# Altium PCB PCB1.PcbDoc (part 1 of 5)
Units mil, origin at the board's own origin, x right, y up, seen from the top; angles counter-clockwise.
Board outline 4463 x 4481 mil, 2 copper layers (Top Layer, Bottom Layer); 0 components, 111 nets, 310 pads, 0 vias.
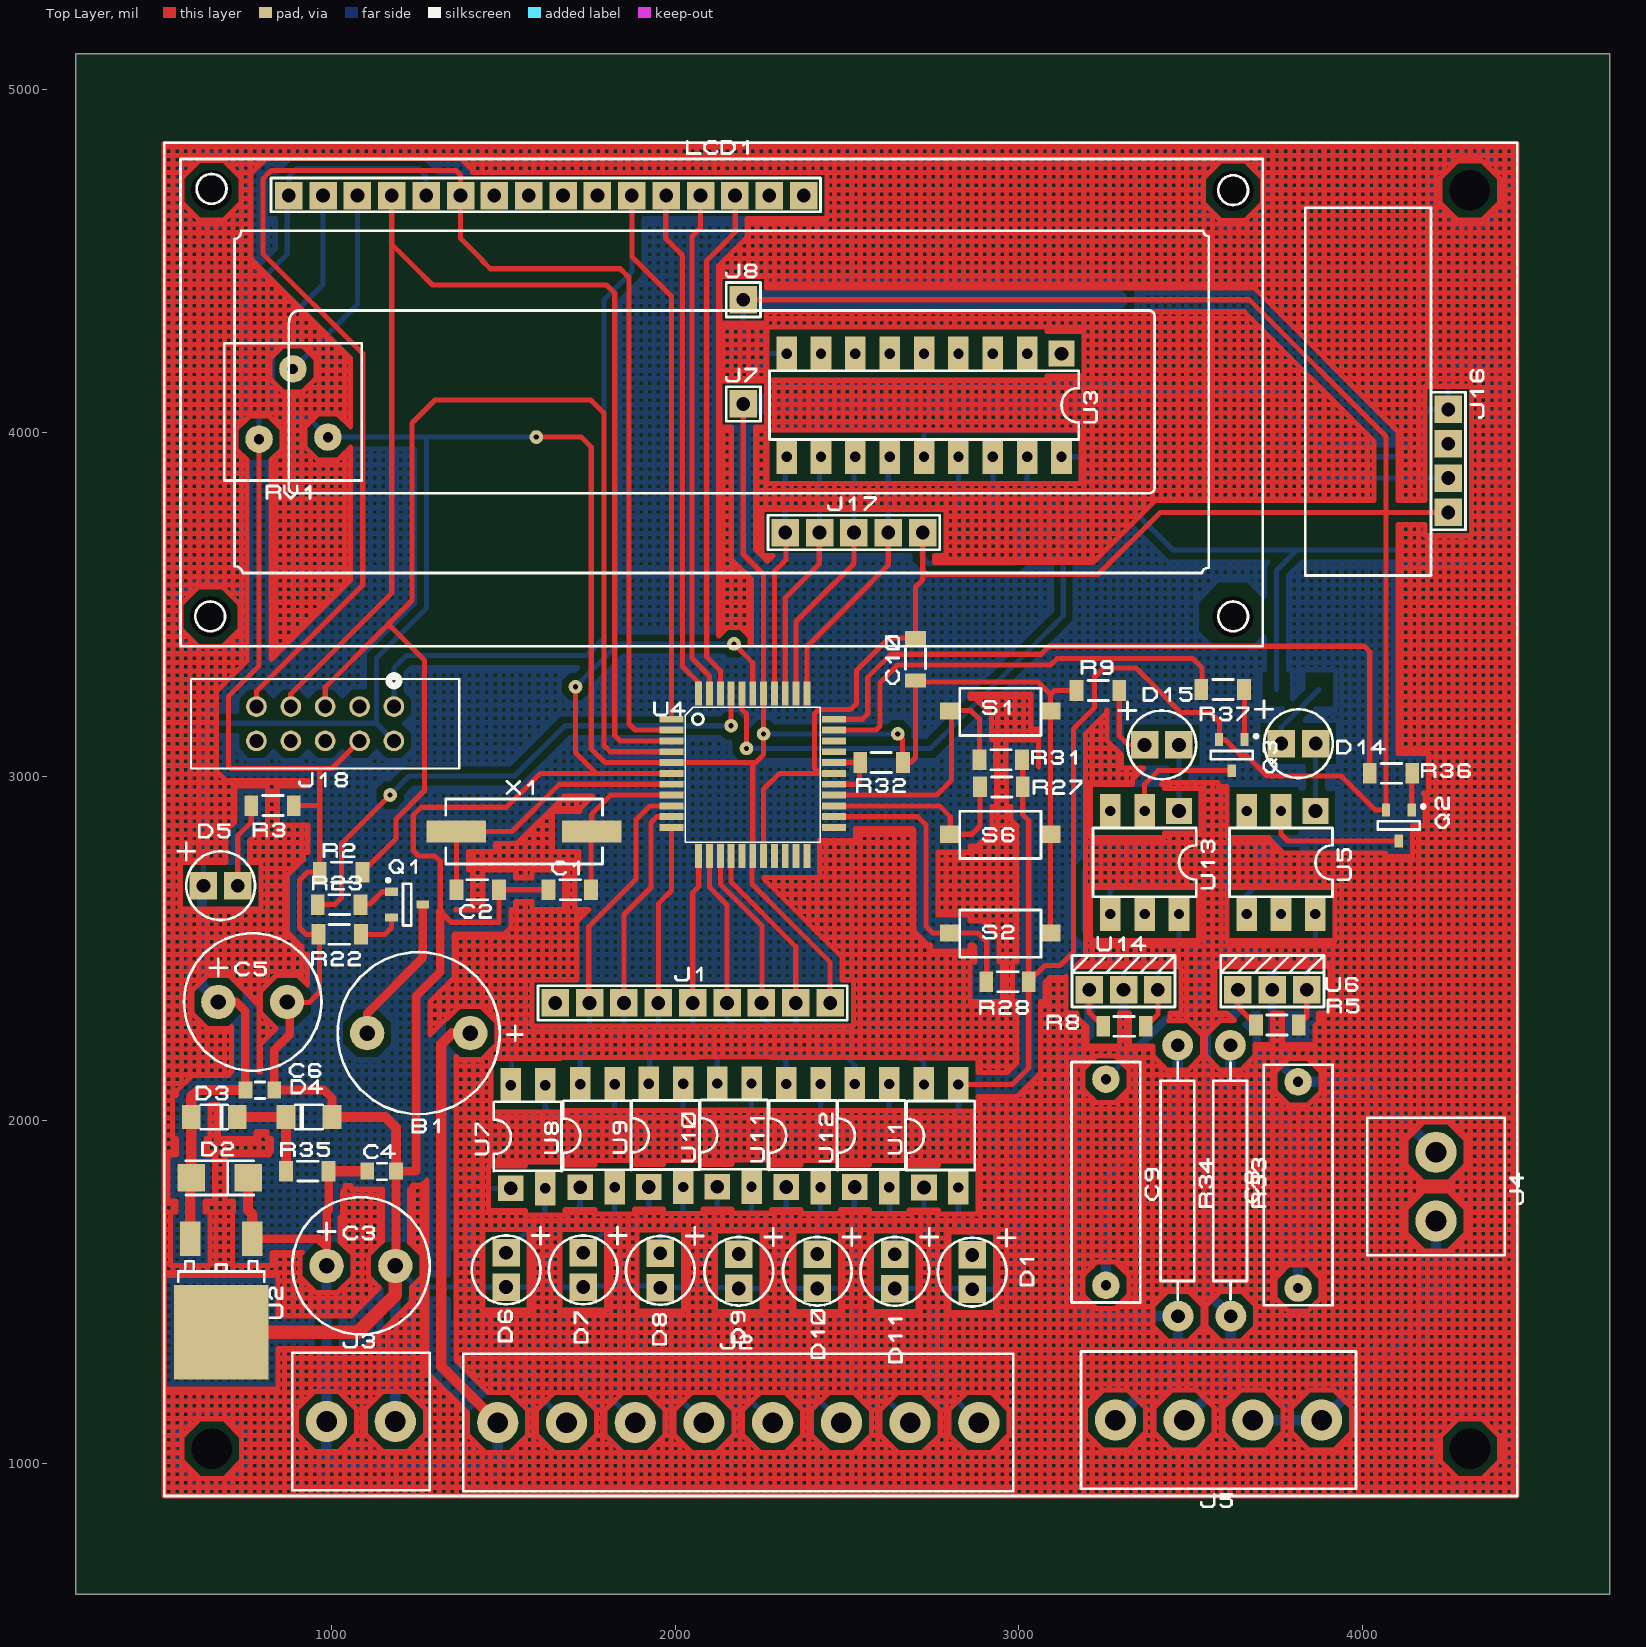
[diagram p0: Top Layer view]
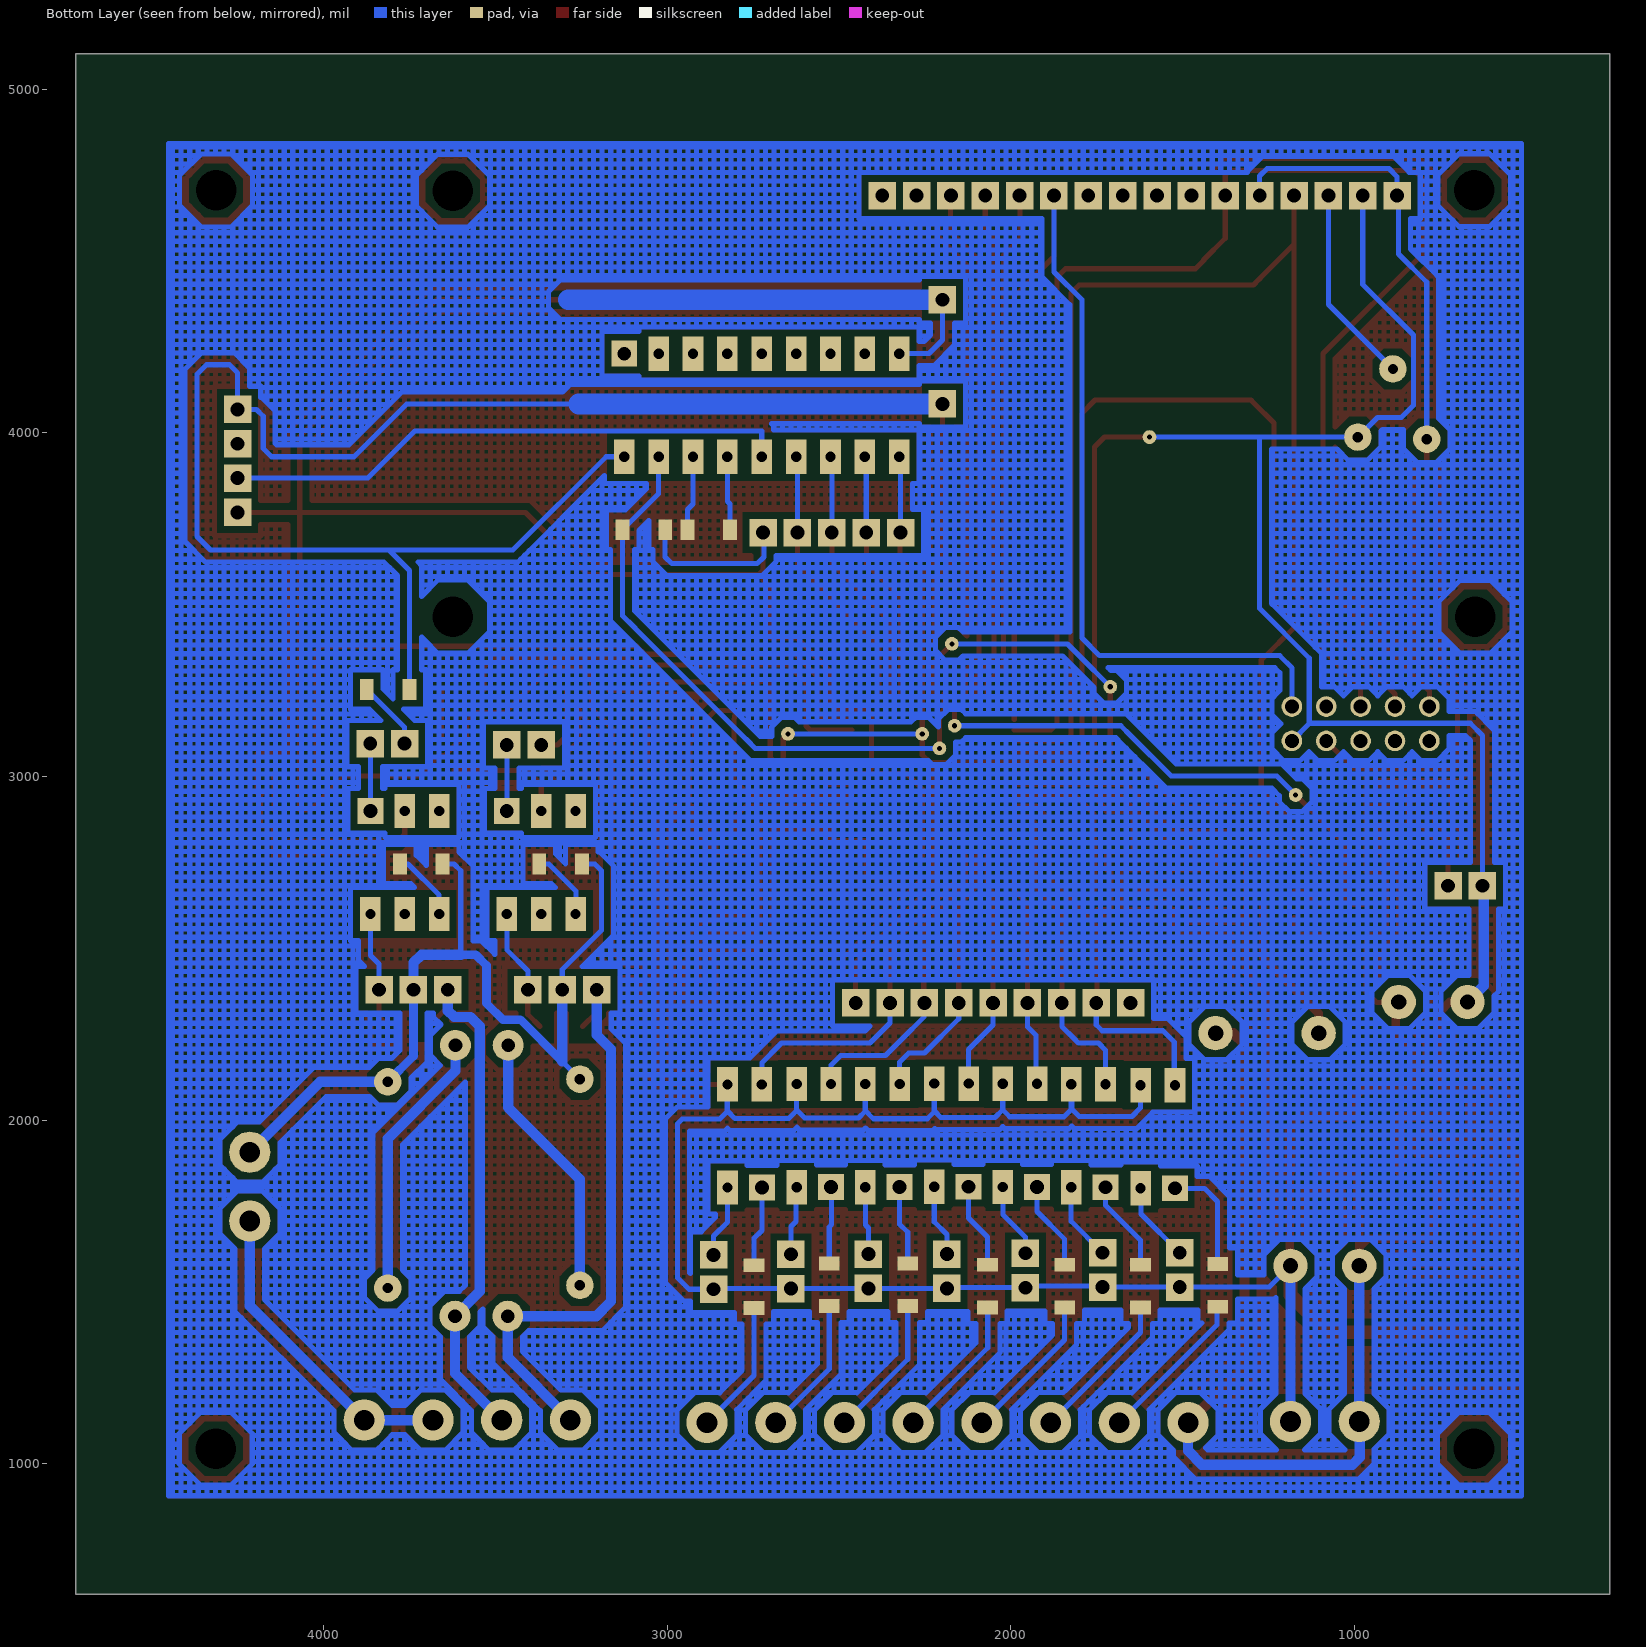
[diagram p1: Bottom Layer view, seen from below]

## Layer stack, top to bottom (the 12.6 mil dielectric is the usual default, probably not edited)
Top Layer: signal copper 1.4
Dielectric: dielectric 12.6, FR-4, Dk 4.8
Bottom Layer: signal copper 1.4

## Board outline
257,621 4720,621 4720,5102 257,5102

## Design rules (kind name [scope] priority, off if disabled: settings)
Clearance CAM_Clearance_2 [OnLayer('Top Layer')] p1: gap=0
Clearance CAM_Clearance_1 [OnLayer('Bottom Layer')] p2: gap=0
Clearance [All] p3: gap=10
PolygonConnect [All] p1: connectstyle=Relief reliefconductorwidth=10 reliefentries=4 polygonreliefangle="90 Angle"
RoutingVias [All] p1: holewidth=28 width=50 viastyle="Through Hole" minholewidth=28 minwidth=50 maxholewidth=28 maxwidth=50
SilkscreenOverComponentPads [All] p1: minsilkscreentomaskgap=10
SolderMaskExpansion [All] p1: expansion=4
Width CAM_Width_2 [OnLayer('Top Layer')] p1: maxlimit=41 minlimit=7 preferedwidth=8
Width CAM_Width_1 [OnLayer('Bottom Layer')] p2: maxlimit=61 minlimit=7 preferedwidth=8
Width [All] p3: maxlimit=10 minlimit=10 preferedwidth=10
27 further rules are at their usual default settings.

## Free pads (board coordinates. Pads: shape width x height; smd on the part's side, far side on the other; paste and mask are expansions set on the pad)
  rect 60x100 smd: 1(589.64,1654.6) 1(769.64,1654.6)
  rect 80x80 smd: 1(592.44,1831.7) 1(758.44,1831.7)
  rect 55x70 smd: 1(592.44,2008.9) 1(726.24,2008.9) 1(868.04,2008.9) 1(1001.84,2008.9)
  rect 80x80 hole 40: 1(627.84,2682.1) 1(727.84,2682.1) 1(875.94,4689.9) 1(975.94,4689.9) 1(1075.94,4689.9) 1(1175.94,4689.9) 1(1275.94,4689.9) 1(1375.94,4689.9) 1(1474.34,4689.9) 1(1508.54,1514) 1(1508.54,1614) 1(1574.34,4689.9) 1(1651.44,2340.8) 1(1674.34,4689.9) 1(1732.94,1514) 1(1732.94,1614) 1(1751.44,2340.8) 1(1774.34,4689.9) 1(1851.44,2340.8) 1(1874.34,4689.9) 1(1951.44,2340.8) 1(1957.34,1512.5) 1(1957.34,1612.5) 1(1974.34,4689.9) 1(2051.44,2340.8) 1(2074.34,4689.9) 1(2151.44,2340.8) 1(2174.34,4689.9) 1(2185.74,1510.1) 1(2185.74,1610.1) 1(2198.74,4083.6) 1(2198.74,4386.8) 1(2251.44,2340.8) 1(2274.34,4689.9) 1(2320.74,3709.6) 1(2351.44,2340.8) 1(2374.34,4689.9) 1(2414.04,1510.1) 1(2414.04,1610.1) 1(2420.74,3709.6) 1(2451.44,2340.8) 1(2520.64,3709.6) 1(2620.64,3709.6) 1(2639.54,1509.7) 1(2639.54,1609.7) 1(2720.64,3709.6) 1(2864.74,1507.7) 1(2864.74,1607.7) 1(3204.94,2379) 1(3304.94,2379) 1(3366.34,3091.5) 1(3404.94,2379) 1(3466.34,3091.5) 1(3638.04,2379) 1(3738.04,2379) 1(3763.94,3095.4) 1(3838.04,2379) 1(3863.94,3095.4) 1(4249.84,3767.9) 1(4249.84,3867.9) 1(4249.84,3967.9) 1(4249.84,4067.9)
  round 0 hole 118.1: 1(648.34,3464.3) 1(651.44,4705.7) 1(652.24,1043.6) 1(3623.44,3464.7) 1(3623.44,4704.1) 1(4312.44,4704.9) 1(4313.24,1043.6)
  round 100 hole 45: 1(671.14,2343.6) 1(871.14,2343.6) 1(986.14,1575.8) 1(1104.24,2253) 1(1186.14,1575.8) 1(1404.24,2253)
  rect 275x275 smd: 1(679.64,1382.6)
  rect 40x50 smd: 1(749.94,2087.6) 1(833.94,2087.6) 1(1104.24,1851.4) 1(1188.24,1851.4)
  rect 40x60 smd: 1(766.84,2915.1) 1(868.04,1851.4) 1(890.84,2915.1) 1(960.54,2627) 1(962.54,2540.4) 1(966.44,2721.5) 1(992.04,1851.4) 1(1084.54,2627) 1(1086.54,2540.4) 1(1090.44,2721.5) 1(1364.04,2670.3) 1(1488.04,2670.3) 1(1631.84,2670.3) 1(1755.84,2670.3) 1(2539.24,3040.3) 1(2663.24,3040.3) 1(2885.64,3048.2) 1(2887.64,2969.4) 1(2905.34,2402.6) 1(3009.64,3048.2) 1(3011.64,2969.4) 1(3029.34,2402.6) 1(3168.34,3250.1) 1(3245.84,2272.7) 1(3292.34,3250.1) 1(3369.84,2272.7) 1(3531.34,3252.9) 1(3655.34,3252.9) 1(3690.74,2276.6) 1(3814.74,2276.6) 1(4021.44,3008.8) 1(4145.44,3008.8)
  round 60 hole 40: 1(782.14,3103.3) 1(782.14,3203.3) 1(882.14,3103.3) 1(882.14,3203.3) 1(982.14,3103.3) 1(982.14,3203.3) 1(1082.14,3103.3) 1(1082.14,3203.3) 1(1182.14,3103.3) 1(1182.14,3203.3)
  round 80 hole 30: 1(789.64,3981.2) 1(888.14,4185.6) 1(990.04,3987.2) 1(3253.74,1519.1) 1(3253.74,2119.1) 1(3812.84,1511.3) 1(3812.84,2111.3)
  round 120 hole 60: 1(986.14,1123.1) 1(1186.14,1123.1) 1(1484.14,1119.9) 1(1684.14,1119.9) 1(1884.14,1119.9) 1(2084.14,1119.9) 1(2284.14,1119.9) 1(2484.04,1119.9) 1(2684.04,1119.9) 1(2884.04,1119.9) 1(3281.34,1127) 1(3481.34,1127) 1(3681.34,1127) 1(3881.34,1127) 1(4214.34,1706.5) 1(4214.34,1906.5)
  round 40 hole 15: 1(1171.14,2945.8) 1(1596.34,3987.2) 1(1710.54,3260.8) 1(2163.34,3147.4) 1(2171.54,3385.6) 1(2207.74,3081.6) 1(2257.74,3123.8) 1(2648.24,3123.8)
  rect 37x24 smd: 1(1175.14,2589.6) 1(1175.14,2664.4) 1(1265.64,2627)
  rect 173x63 smd: 1(1364.04,2839.6) 1(1757.74,2839.6)
  rect 60x40 smd far side: 1(1398.34,1457) 1(1398.34,1581) 1(1622.74,1455) 1(1622.74,1579) 1(1843.24,1455) 1(1843.24,1579) 1(2067.64,1455) 1(2067.64,1579) 1(2299.94,1458.9) 1(2299.94,1582.9) 1(2528.14,1458.9) 1(2528.14,1582.9) 1(2747.04,1453.4) 1(2747.04,1577.4)
  rect 75x75 hole 40: 1(1522.34,1801.4) 1(1724.34,1804.6) 1(1923.54,1805.4) 1(2122.74,1806.2) 1(2323.54,1805) 1(2523.04,1805) 1(2724.24,1803.8) 1(3124.64,4230.1) 1(3466.34,2899.4) 1(3863.24,2899.4)
  rect 60x100 hole 30: 1(1522.34,2101.4) 1(1622.34,1801.4) 1(1622.34,2101.4) 1(1724.34,2104.6) 1(1824.34,1804.6) 1(1824.34,2104.6) 1(1923.54,2105.4) 1(2023.54,1805.4) 1(2023.54,2105.4) 1(2122.74,2106.2) 1(2222.74,1806.2) 1(2222.74,2106.2) 1(2323.54,2105) 1(2324.74,3930.1) 1(2324.74,4230.1) 1(2423.54,1805) 1(2423.54,2105) 1(2424.74,3930.1) 1(2424.74,4230.1) 1(2523.04,2105) 1(2524.64,3930.1) 1(2524.64,4230.1) 1(2623.04,1805) 1(2623.04,2105) 1(2624.64,3930.1) 1(2624.64,4230.1) 1(2724.24,2103.8) 1(2724.64,3930.1) 1(2724.64,4230.1) 1(2824.24,1803.8) 1(2824.24,2103.8) 1(2824.64,3930.1) 1(2824.64,4230.1) 1(2924.64,3930.1) 1(2924.64,4230.1) 1(3024.64,3930.1) 1(3024.64,4230.1) 1(3124.64,3930.1) 1(3266.34,2599.5) 1(3266.34,2899.4) 1(3366.34,2599.5) 1(3366.34,2899.4) 1(3466.34,2599.5) 1(3663.24,2599.5) 1(3663.24,2899.4) 1(3763.24,2599.5) 1(3763.24,2899.4) 1(3863.24,2599.5)
  rect 70x20 smd: 1(1990.04,2851.4) 1(1990.04,2882.8) 1(1990.04,2914.3) 1(1990.04,2945.8) 1(1990.04,2977.3) 1(1990.04,3008.8) 1(1990.04,3040.3) 1(1990.04,3071.8) 1(1990.04,3103.3) 1(1990.04,3134.8) 1(1990.04,3166.3) 1(2462.54,2851.4) 1(2462.54,2882.8) 1(2462.54,2914.3) 1(2462.54,2945.8) 1(2462.54,2977.3) 1(2462.54,3008.8) 1(2462.54,3040.3) 1(2462.54,3071.8) 1(2462.54,3103.3) 1(2462.54,3134.8) 1(2462.54,3166.3)
  rect 20x70 smd: 1(2068.84,2768.8) 1(2068.84,3241.1) 1(2100.34,2768.8) 1(2100.34,3241.1) 1(2131.84,2768.8) 1(2131.84,3241.1) 1(2163.34,2768.8) 1(2163.34,3241.1) 1(2194.74,2768.8) 1(2194.74,3241.1) 1(2226.24,2768.8) 1(2226.24,3241.1) 1(2257.74,2768.8) 1(2257.74,3241.1) 1(2289.24,2768.8) 1(2289.24,3241.1) 1(2320.74,2768.8) 1(2320.74,3241.1) 1(2352.24,2768.8) 1(2352.24,3241.1) 1(2383.74,2768.8) 1(2383.74,3241.1)
  rect 60x40 smd: 1(2699.84,3278.9) 1(2699.84,3402.9)
  rect 60x50 smd: 1(2800.94,2544.3) 1(2800.94,2831.7) 1(2800.94,3189.9) 1(3092.34,2544.3) 1(3092.34,2831.7) 1(3092.34,3189.9)
  rect 40x60 smd far side: 1(2816.74,3717.5) 1(2940.74,3717.5) 1(3005.74,3717.5) 1(3129.74,3717.5) 1(3247.84,2745.1) 1(3371.84,2745.1) 1(3653.34,2745.1) 1(3749.84,3252.9) 1(3777.34,2745.1) 1(3873.84,3252.9)
  round 90 hole 40: 1(3462.44,2217.6) 1(3463.64,1429.5) 1(3615.94,2217.6) 1(3617.14,1429.5)
  rect 24x37 smd: 1(3582.44,3107.2) 1(3619.84,3016.7) 1(3657.24,3107.2) 1(4068.74,2902.5) 1(4106.14,2812.1) 1(4143.54,2902.5)

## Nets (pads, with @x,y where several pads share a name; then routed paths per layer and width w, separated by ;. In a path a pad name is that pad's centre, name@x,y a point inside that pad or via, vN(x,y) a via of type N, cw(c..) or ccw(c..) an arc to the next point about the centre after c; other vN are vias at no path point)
$Net1: pad.1@960.54,2627 pad.1@1171.14,2945.8 pad.1@2163.34,3147.4 pad.1@2163.34,3241.1 | length 1604.3
  Top Layer w15: pad.1@960.54,2627 1009.74,2627 1029.44,2646.7 1029.44,2804.2 pad.1@1171.14,2945.8 ; pad.1@2163.34,3147.4 pad.1@2163.34,3241.1
  Bottom Layer w15: pad.1@1171.14,2945.8 1226.24,3000.9 1533.34,3000.9 1651.44,3119 1679.84,3147.4 pad.1@2163.34,3147.4
$Net2: pad.1@2194.74,3241.1 pad.1@2207.74,3081.6 pad.1@3024.64,3930.1 pad.1@3129.74,3717.5 | length 1752.9
  Top Layer w15: pad.1@2194.74,3241.1 2194.74,3194.2 2207.74,3181.2 pad.1@2207.74,3081.6
  Bottom Layer w15: pad.1@2207.74,3081.6 2743.94,3081.6 2766.34,3104.1 2778.94,3116.7 3084.44,3422.2 3098.04,3435.8 3129.74,3467.5 3129.74,3468.7 3129.74,3505.7 pad.1@3129.74,3717.5 3024.64,3822.6 pad.1@3024.64,3930.1
$Net4: pad.1@758.44,1831.7 pad.1@769.64,1654.6 pad.1@986.14,1123.1 pad.1@986.14,1575.8 pad.1@992.04,1851.4 pad.1@1104.24,1851.4 pad.1@1404.24,2253 pad.1@1484.14,1119.9 | length 3229.6
  Top Layer w15: pad.1@986.14,1575.8 986.14,1630.6
  Top Layer w25: pad.1@769.64,1654.6 950.14,1654.6 962.14,1654.6 986.14,1630.6 986.14,1733.2 992.04,1739 pad.1@992.04,1851.4
  Top Layer w30: pad.1@758.44,1831.7 757.74,1791.7 757.74,1737.3 769.64,1725.4 pad.1@769.64,1654.6 ; pad.1@992.04,1851.4 pad.1@1104.24,1851.4 ; pad.1@1404.24,2253 1352.24,2253 1319.94,2220.7 1319.94,1284.1 pad.1@1484.14,1119.9
  Bottom Layer w30: pad.1@986.14,1575.8 pad.1@986.14,1123.1 984.94,1063.1 984.94,1018.4 1005.84,997.5 1444.44,997.5 1484.14,1037.3 pad.1@1484.14,1119.9
$Net6: pad.1@3247.84,2745.1 pad.1@3253.74,2119.1 pad.1@3304.94,2379 pad.1@3653.34,2745.1 pad.1@3738.04,2379 pad.1@3812.84,2111.3 pad.1@4214.34,1906.5 | length 2545.5
  Bottom Layer w15: pad.1@3247.84,2745.1 3210.44,2745.1 3190.74,2725.4 3190.74,2552.2 3304.94,2438 pad.1@3304.94,2379 ; pad.1@3253.74,2119.1 3304.94,2170.3 ; 3600.24,2481.3 3600.24,2725.4 3619.84,2745.1 pad.1@3653.34,2745.1
  Bottom Layer w25: 3304.94,2170.3 3426.94,2292.4 3478.14,2292.4 3525.44,2339.6 3525.44,2449.9 3556.94,2481.3 3600.24,2481.3 ; pad.1@3738.04,2379 3738.04,2339 3738.04,2186.1 pad.1@3812.84,2111.3
  Bottom Layer w30: 3304.94,2170.3 3304.94,2339 pad.1@3304.94,2379 ; 3600.24,2481.3 3714.34,2481.3 3738.04,2457.7 pad.1@3738.04,2379 ; pad.1@3812.84,2111.3 4009.64,2111.3 pad.1@4214.34,1906.5
$Net7: pad.1@3681.34,1127 pad.1@3881.34,1127 pad.1@4214.34,1706.5 | length 917.4
  Bottom Layer w30: pad.1@3681.34,1127 3821.34,1127 pad.1@3881.34,1127 4214.34,1460.1 pad.1@4214.34,1706.5
$Net8: pad.1@3481.34,1127 pad.1@3617.14,1429.5 pad.1@3638.04,2379 pad.1@3690.74,2276.6 | length 1528.5
  Top Layer w15: pad.1@3638.04,2379 3638.04,2339 3638.04,2329.4 pad.1@3690.74,2276.6
  Bottom Layer w30: pad.1@3481.34,1127 3617.14,1262.9 pad.1@3617.14,1429.5 3545.04,1501.5 3545.04,2272.7 3572.64,2300.2 3619.84,2300.2 3638.04,2318.4 pad.1@3638.04,2379
$Net9: pad.1@3204.94,2379 pad.1@3245.84,2272.7 pad.1@3281.34,1127 pad.1@3463.64,1429.5 | length 1743.1
  Top Layer w15: pad.1@3204.94,2379 3204.94,2313.6 pad.1@3245.84,2272.7
  Bottom Layer w30: pad.1@3204.94,2379 3204.94,2247.5 3163.24,2205.8 3163.24,1472.8 3206.54,1429.5 pad.1@3463.64,1429.5 3463.64,1309.3 pad.1@3281.34,1127
$Net10: pad.1@1398.34,1457 pad.1@1684.14,1119.9 | length 454.9
  Bottom Layer w15: pad.1@1398.34,1457 1399.94,1437 1399.94,1404.2 pad.1@1684.14,1119.9
$Net11: pad.1@1622.74,1455 pad.1@1884.14,1119.9 | length 443.1
  Bottom Layer w15: pad.1@1622.74,1455 1622.74,1382.1 1824.94,1179.9 pad.1@1884.14,1119.9
$Net12: pad.1@1843.24,1455 pad.1@2084.14,1119.9 | length 434.7
  Bottom Layer w15: pad.1@1843.24,1455 1843.64,1435 1843.64,1360.5 pad.1@2084.14,1119.9
$Net13: pad.1@2067.64,1455 pad.1@2284.14,1119.9 | length 425.1
  Bottom Layer w15: pad.1@2067.64,1455 2066.84,1435 2066.84,1337.3 pad.1@2284.14,1119.9
$Net14: pad.1@2299.94,1458.9 pad.1@2484.04,1119.9 | length 415.2
  Bottom Layer w15: pad.1@2299.94,1458.9 2299.94,1304.2 pad.1@2484.04,1119.9
$Net15: pad.1@2528.14,1458.9 pad.1@2684.04,1119.9 | length 403.6
  Bottom Layer w15: pad.1@2528.14,1458.9 2528.14,1275.8 pad.1@2684.04,1119.9
$Net16: pad.1@2747.04,1453.4 pad.1@2884.04,1119.9 | length 390.2
  Bottom Layer w15: pad.1@2747.04,1453.4 2747.04,1256.9 pad.1@2884.04,1119.9
$Net17: pad.1@1104.24,2253 pad.1@1265.64,2627 | length 441
  Top Layer w25: pad.1@1104.24,2253 1104.24,2310.5 1266.04,2472.3 1266.04,2615 pad.1@1265.64,2627
$Net18: pad.1@727.84,2682.1 pad.1@766.84,2915.1 | length 249.2
  Top Layer w15: pad.1@727.84,2682.1 727.84,2827.4 766.84,2866.4 pad.1@766.84,2915.1
$Net19: pad.1@1398.34,1581 pad.1@1522.34,1801.4 | length 322
  Bottom Layer w15: pad.1@1398.34,1581 1398.34,1636.9 1398.34,1763.2 1436.54,1801.4 pad.1@1522.34,1801.4
$Net20: pad.1@1622.74,1579 pad.1@1724.34,1804.6 | length 267.7
  Bottom Layer w15: pad.1@1622.74,1579 1622.74,1650.6 1724.34,1752.2 pad.1@1724.34,1804.6
$Net21: pad.1@1843.24,1579 pad.1@1923.54,1805.4 | length 259.7
  Bottom Layer w15: pad.1@1843.24,1579 1843.24,1653.4 1923.54,1733.7 pad.1@1923.54,1805.4
$Net22: pad.1@2067.64,1579 pad.1@2122.74,1806.2 | length 250
  Bottom Layer w15: pad.1@2067.64,1579 2067.64,1660.1 2122.74,1715.2 pad.1@2122.74,1806.2
$Net23: pad.1@2299.94,1582.9 pad.1@2323.54,1805 | length 231.9
  Bottom Layer w15: pad.1@2299.94,1582.9 2299.94,1673.5 2323.54,1697.1 pad.1@2323.54,1805
$Net24: pad.1@2523.04,1805 pad.1@2528.14,1582.9 | length 224.9
  Bottom Layer w15: pad.1@2523.04,1805 2521.44,1767.5 2521.44,1695.9 2528.14,1689.2 pad.1@2528.14,1582.9
$Net25: pad.1@1508.54,1614 pad.1@1622.34,1801.4 | length 234.1
  Bottom Layer w15: pad.1@1508.54,1614 1621.14,1726.6 1621.14,1751.4 pad.1@1622.34,1801.4
$Net26: pad.1@1732.94,1614 pad.1@1824.34,1804.6 | length 228.5
  Bottom Layer w15: pad.1@1732.94,1614 1824.34,1705.4 pad.1@1824.34,1804.6
$Net27: pad.1@1957.34,1612.5 pad.1@2023.54,1805.4 | length 220.2
  Bottom Layer w15: pad.1@1957.34,1612.5 1957.34,1659.3 2023.14,1725 2023.14,1755.4 pad.1@2023.54,1805.4
$Net28: pad.1@2185.74,1610.1 pad.1@2222.74,1806.2 | length 211.4
  Bottom Layer w15: pad.1@2185.74,1610.1 2185.74,1667.2 2222.74,1704.2 pad.1@2222.74,1806.2
$Net29: pad.1@2414.04,1610.1 pad.1@2423.54,1805 | length 198.7
  Bottom Layer w15: pad.1@2414.04,1610.1 2414.04,1686.1 2423.14,1695.1 2423.14,1755 pad.1@2423.54,1805
$Net30: pad.1@2623.04,1805 pad.1@2639.54,1609.7 | length 201.5
  Bottom Layer w15: pad.1@2623.04,1805 2624.64,1755 2624.64,1705 2639.54,1690 2639.54,1649.7 pad.1@2639.54,1609.7
$Net31: pad.1@3615.94,2217.6 pad.1@3812.84,1511.3 | length 787.9
  Bottom Layer w30: pad.1@3615.94,2217.6 3615.94,2142.8 3812.84,1945.9 3812.84,1551.3 pad.1@3812.84,1511.3
$Net32: pad.1@3253.74,1519.1 pad.1@3462.44,2217.6 | length 784.9
  Bottom Layer w30: pad.1@3253.74,1519.1 3253.74,1827.8 3462.44,2036.5 pad.1@3462.44,2217.6
$Net33: pad.1@3814.74,2276.6 pad.1@3838.04,2379 pad.1@3863.24,2599.5 | length 343
  Top Layer w15: pad.1@3814.74,2276.6 3838.04,2299.9 pad.1@3838.04,2379
  Bottom Layer w15: pad.1@3838.04,2379 3838.04,2453.8 3863.24,2479 pad.1@3863.24,2599.5
$Net34: pad.1@3369.84,2272.7 pad.1@3404.94,2379 pad.1@3466.34,2599.5 | length 367
  Top Layer w15: pad.1@3369.84,2272.7 3405.34,2308.1 3405.34,2339 pad.1@3404.94,2379
  Bottom Layer w15: pad.1@3404.94,2379 3404.94,2434.1 3466.34,2495.5 pad.1@3466.34,2599.5
$Net35: pad.1@3863.24,2899.4 pad.1@3863.94,3095.4 | length 196
  Bottom Layer w15: pad.1@3863.24,2899.4 3863.24,3055.4 pad.1@3863.94,3095.4
$Net36: pad.1@3466.34,2899.4 pad.1@3466.34,3091.5 | length 192.1
  Bottom Layer w15: pad.1@3466.34,2899.4 pad.1@3466.34,3091.5
$Net37: pad.1@3763.94,3095.4 pad.1@3873.84,3252.9 | length 203.1
  Bottom Layer w15: pad.1@3763.94,3095.4 3763.94,3143.1 pad.1@3873.84,3252.9
$Net38: pad.1@3292.34,3250.1 pad.1@3366.34,3091.5 | length 216.9
  Top Layer w15: pad.1@3292.34,3250.1 3292.34,3118.3 3319.14,3091.5 pad.1@3366.34,3091.5
$Net39: pad.1@589.64,1654.6 pad.1@592.44,1831.7 pad.1@592.44,2008.9 pad.1@627.84,2682.1 pad.1@671.14,2343.6 pad.1@749.94,2087.6 pad.1@975.94,4689.9 pad.1@990.04,3987.2 pad.1@1182.14,3103.3 pad.1@1596.34,3987.2 pad.1@1990.04,3040.3 pad.1@2198.74,4083.6 pad.1@2226.24,2768.8 pad.1@2257.74,3123.8 pad.1@2257.74,3241.1 pad.1@2451.44,2340.8 pad.1@2648.24,3123.8 pad.1@2663.24,3040.3 pad.1@2699.84,3278.9 pad.1@3092.34,2544.3 pad.1@3092.34,2831.7 pad.1@3092.34,3189.9 pad.1@3124.64,3930.1 pad.1@3168.34,3250.1 pad.1@3749.84,3252.9 pad.1@4249.84,4067.9 | length 14746.2
  Top Layer w15: pad.1@1596.34,3987.2 1727.44,3987.2 1756.24,3958.4 1756.24,3080.1 1795.94,3040.3 pad.1@1990.04,3040.3 2025.04,3040.3 2041.24,3040.3 2226.24,3040.3 ; pad.1@2198.74,4083.6 2198.74,4043.6 2198.74,3895.4 2198.74,3887.2 2198.74,3646.6 2206.64,3638.7 2257.74,3587.5 pad.1@2257.74,3241.1 2257.74,3206.1 2257.74,3193.8 pad.1@2257.74,3123.8 2257.74,3123.4 2257.74,3063.1 2234.94,3040.3 2226.24,3040.3 ; pad.1@2451.44,2340.8 2451.44,2424.3 2451.44,2459.3 2287.34,2623.5 2261.74,2649.1 2224.34,2686.5 2224.34,2733.8 pad.1@2226.24,2768.8 2226.24,2823.9 2226.24,3040.3 ; pad.1@2648.24,3123.8 2662.04,3110 2662.04,3070.3 pad.1@2663.24,3040.3 2685.24,3040.3 2699.84,3054.9 pad.1@2699.84,3278.9 2729.84,3274.6 3055.74,3274.6 3092.34,3237.9 ; pad.1@3092.34,2544.3 pad.1@3092.34,2831.7 pad.1@3092.34,3189.9 3092.34,3237.9 ; pad.1@3168.34,3250.1 3104.54,3250.1 3092.34,3237.9
  Top Layer w25: pad.1@671.14,2343.6 723.14,2343.6 749.94,2316.8 749.94,2274.7 pad.1@749.94,2087.6
  Top Layer w30: pad.1@589.64,1654.6 589.64,1791.7 pad.1@592.44,1831.7 592.44,1973.9 pad.1@592.44,2008.9 592.44,2068 612.14,2087.6 pad.1@749.94,2087.6
  Bottom Layer w15: pad.1@627.84,2682.1 627.84,3119 663.34,3154.5 1131.44,3154.5 ; pad.1@975.94,4689.9 975.94,4431.6 828.64,4284.4 828.64,4079.7 864.04,4044.2 932.94,4044.2 pad.1@990.04,3987.2 1276.64,3987.2 ; pad.1@1182.14,3103.3 1131.44,3154.1 1131.44,3154.5 ; pad.1@1596.34,3987.2 1276.64,3987.2 ; pad.1@2257.74,3123.8 pad.1@2648.24,3123.8 ; pad.1@3124.64,3930.1 3177.34,3930.1 3449.04,3658.4 3808.84,3658.4 ; 3257.64,4083.6 3757.64,4083.6 3911.24,3930.1 4151.34,3930.1 4175.04,3953.7 4175.04,4048.2 4194.64,4067.9 pad.1@4249.84,4067.9 4249.84,4174.2 4273.44,4197.8 4340.34,4197.8 4367.94,4170.2 4367.94,3697.8 4328.54,3658.4 3869.84,3658.4 3808.84,3658.4 ; pad.1@3749.84,3252.9 3749.84,3282.9 3749.84,3304.1 3749.84,3599.4 3808.84,3658.4 ; 1131.44,3154.5 1131.44,3343.8 1276.64,3489.1 1276.64,3987.2
  Bottom Layer w30: pad.1@627.84,2682.1 623.94,2642.1 623.94,2390.8 pad.1@671.14,2343.6
  Bottom Layer w60: pad.1@2198.74,4083.6 3226.14,4083.6 3257.64,4083.6
$Net40: pad.1@4249.84,3967.9
$Net41: pad.1@2724.64,3930.1 pad.1@4249.84,3867.9 | length 1656.7
  Bottom Layer w15: pad.1@2724.64,3930.1 2724.64,4004.9 3734.04,4004.9 3871.04,3867.9 pad.1@4249.84,3867.9
$Net43: pad.1@1182.14,3203.3 pad.1@1874.34,4689.9 pad.1@1990.04,3166.3 | length 3652.1
  Top Layer w15: pad.1@1874.34,4689.9 1874.34,4649.9 1874.34,4530.1 1874.34,4520.6 1874.34,4512.7 1990.04,4397 pad.1@1990.04,3166.3
  Bottom Layer w15: pad.1@1182.14,3203.3 1182.14,3315.9 1217.64,3351.3 1742.04,3351.3 1793.24,3402.5 1793.24,4386.8 1874.34,4467.9 1874.34,4482.4 1874.34,4490.7 1874.34,4649.9 pad.1@1874.34,4689.9
$Net44: pad.1@1082.14,3203.3
$Net45: pad.1@982.14,3203.3 pad.1@1090.44,2721.5 pad.1@1990.04,3071.8 | length 3545.4
  Top Layer w15: pad.1@982.14,3203.3 982.14,3259.2 1138.64,3415.7 1145.94,3423 1160.94,3437.9 ; pad.1@1090.44,2721.5 1187.74,2818.8 1187.74,2875.3 1271.14,2958.8 1271.14,3337.9 1221.54,3387.5 1219.24,3389.9 1210.54,3398.6 1171.14,3437.9 1160.94,3437.9 ; pad.1@1990.04,3071.8 1955.04,3071.8 1811.34,3071.8 1793.24,3089.9 1793.24,4056.4 1754.64,4095 1506.24,4095 1301.44,4095 1292.84,4086.4 1234.54,4028.1 1234.54,3557.2 1234.54,3511.6 1185.54,3462.5 1160.94,3437.9
$Net46: pad.1@982.14,3103.3
$Net47: pad.1@882.14,3203.3 pad.1@1175.94,4689.9 pad.1@1990.04,3103.3 | length 3775.1
  Top Layer w15: pad.1@882.14,3203.3 882.14,3239.9 1175.94,3533.6 1175.94,4548.2 ; pad.1@1175.94,4689.9 1175.94,4548.2 ; pad.1@1990.04,3103.3 1840.44,3103.3 1824.74,3119 1824.74,4406.4 1801.04,4430.1 1294.04,4430.1 1278.24,4445.8 1269.04,4455.1 1175.94,4548.2
$Net48: pad.1@882.14,3103.3
$Net49: pad.1@782.14,3203.3 pad.1@1375.94,4689.9 pad.1@1990.04,3134.8 | length 4528.5
  Top Layer w15: pad.1@782.14,3203.3 782.14,3247.8 1091.24,3556.8 1091.24,4230.5 800.74,4521 800.74,4738.7 825.14,4763.1 1362.94,4763.1 1375.94,4750.1 pad.1@1375.94,4689.9 1375.94,4565.9 1439.24,4502.5 1438.34,4501.5 1462.54,4477.3 1840.44,4477.3 1846.34,4471.4 1866.04,4451.7 1866.04,3152.5 1883.74,3134.8 pad.1@1990.04,3134.8
$Net50: pad.1@782.14,3103.3
$Net51: pad.1@679.64,1382.6 pad.1@789.64,3981.2 pad.1@833.94,2087.6 pad.1@871.14,2343.6 pad.1@875.94,4689.9 pad.1@890.84,2915.1 pad.1@962.54,2540.4 pad.1@966.44,2721.5 pad.1@1001.84,2008.9 pad.1@1082.14,3103.3 pad.1@1186.14,1123.1 pad.1@1186.14,1575.8 pad.1@1188.24,1851.4 pad.1@1275.94,4689.9 pad.1@1488.04,2670.3 pad.1@1508.54,1514 pad.1@1622.34,2101.4 pad.1@1631.84,2670.3 pad.1@1710.54,3260.8 pad.1@1732.94,1514 pad.1@1824.34,2104.6 pad.1@1957.34,1512.5 pad.1@1990.04,3008.8 pad.1@2023.54,2105.4 pad.1@2171.54,3385.6 pad.1@2185.74,1510.1 pad.1@2198.74,4386.8 pad.1@2222.74,2106.2 pad.1@2226.24,3241.1 pad.1@2257.74,2768.8 pad.1@2324.74,4230.1 pad.1@2414.04,1510.1 pad.1@2423.54,2105 pad.1@2462.54,3008.8 pad.1@2623.04,2105 pad.1@2639.54,1509.7 pad.1@2699.84,3402.9 pad.1@2720.64,3709.6 pad.1@2824.24,2103.8 pad.1@2864.74,1507.7 pad.1@3005.74,3717.5 pad.1@3009.64,3048.2 pad.1@3011.64,2969.4 pad.1@3029.34,2402.6 pad.1@3582.44,3107.2 pad.1@4068.74,2902.5 pad.1@4249.84,3767.9 | length 24743.1
  Top Layer w15: pad.1@789.64,3981.2 789.64,3321.8 700.34,3232.4 700.34,3030.1 707.04,3023.4 966.44,3023.4 ; pad.1@871.14,2343.6 921.14,2342.4 935.74,2342.4 965.64,2372.3 965.64,2510.4 pad.1@962.54,2540.4 927.04,2540.4 907.34,2560.1 907.34,2697.9 931.04,2721.5 pad.1@966.44,2721.5 966.44,2915.1 ; pad.1@890.84,2915.1 966.44,2915.1 ; pad.1@1082.14,3103.3 1002.24,3023.4 970.74,3023.4 966.44,3023.4 ; pad.1@1631.84,2670.3 pad.1@1488.04,2670.3 1488.04,2575.8 1348.34,2575.8 1324.74,2599.5 1316.84,2607.3 1316.84,2621.9 1316.84,2753 1301.04,2768.8 1253.84,2768.8 1238.14,2784.5 1238.14,2886.8 1261.74,2910.4 1434.94,2910.4 1509.74,2910.4 1547.14,2947.8 1608.14,3008.8 1710.54,3008.8 1770.74,3008.8 ; pad.1@1710.54,3260.8 1710.54,3095 1710.54,3069 1770.74,3008.8 ; pad.1@1990.04,3008.8 1770.74,3008.8 ; pad.1@2171.54,3385.6 2226.24,3330.9 pad.1@2226.24,3241.1 ; pad.1@2198.74,4386.8 3671.04,4386.8 4068.74,3989.1 4068.74,3854.9 4068.74,3835.6 4068.74,3820.2 4068.74,3767.9 ; pad.1@2257.74,2768.8 2257.74,2963.1 2303.44,3008.8 2420.34,3008.8 ; pad.1@2462.54,3008.8 2420.34,3008.8 ; pad.1@2720.64,3709.6 2720.64,3599.8 ; pad.1@2824.24,2103.8 2981.34,2103.8 3029.34,2151.8 3029.34,2372.6 pad.1@3029.34,2402.6 ; pad.1@3009.64,3048.2 3011.64,3018.2 pad.1@3011.64,2969.4 3011.64,2888.7 3029.34,2871.1 3029.34,2587.6 3029.34,2575.8 pad.1@3029.34,2402.6 ; 3220.44,3294.6 3220.44,3288.9 ; pad.1@4249.84,3767.9 4071.84,3767.9 4068.74,3767.9 ; 966.44,2915.1 966.44,3023.4 ; 2420.34,3008.8 2405.44,3023.8 2405.44,3182 2417.64,3194.2 2510.84,3194.2 2527.74,3211.2 2527.74,3308 2622.24,3402.5 2669.84,3402.5 pad.1@2699.84,3402.9 2699.84,3550.9 2720.64,3571.8 2720.64,3599.8 ; 2720.64,3599.8 2733.24,3587.2 3230.94,3587.2 3411.64,3767.9 4068.74,3767.9 ; pad.1@3029.34,2402.6 3076.54,2449.9 3119.84,2449.9 3159.24,2489.2 3159.24,3138.7 3220.44,3200 3220.44,3276.9 3220.44,3288.9 ; 3220.44,3288.9 3247.44,3315.9 3290.74,3315.9 3341.14,3315.9 3360.24,3296.8 3378.14,3278.9 3471.04,3186 3556.94,3186 3584.44,3158.4 3584.44,3125.7 pad.1@3582.44,3107.2 3600.24,3107.2 3647.44,3060 3663.24,3060 3722.24,3000.9 3938.74,3000.9 4037.24,2902.5 pad.1@4068.74,2902.5 4068.74,3680.1 4068.74,3693.1 4068.74,3767.9
  Top Layer w25: pad.1@871.14,2343.6 879.44,2293.6 879.44,2249.7 833.94,2204.2 pad.1@833.94,2087.6 978.24,2087.6 1001.84,2064 pad.1@1001.84,2008.9 ; pad.1@1186.14,1575.8 1188.24,1625.8 pad.1@1188.24,1851.4 1247.14,1851.4 1247.14,2360.9 1316.84,2430.6 1316.84,2607.3
  Top Layer w30: pad.1@1001.84,2008.9 1156.74,2008.9 1188.24,1977.4 pad.1@1188.24,1851.4
  Top Layer w40: pad.1@679.64,1382.6 1077.64,1382.6 1186.14,1491 pad.1@1186.14,1575.8
  Bottom Layer w15: pad.1@789.64,3981.2 789.64,4437.9 871.94,4520.2 871.94,4649.9 pad.1@875.94,4689.9 875.94,4745 899.54,4768.7 1253.84,4768.7 1275.94,4746.6 pad.1@1275.94,4689.9 ; pad.1@1186.14,1575.8 1247.94,1514 pad.1@1508.54,1514 1692.94,1514 pad.1@1732.94,1514 1772.94,1516.8 1917.34,1516.8 pad.1@1957.34,1512.5 2145.74,1512.5 pad.1@2185.74,1510.1 2374.04,1510.1 pad.1@2414.04,1510.1 2599.54,1510.1 pad.1@2639.54,1509.7 2824.74,1509.7 pad.1@2864.74,1507.7 2936.04,1507.7 2969.54,1541.2 2969.54,1989.6 2955.74,2003.4 2846.74,2003.4 2824.24,2026 2824.24,2026.1 ; pad.1@1622.34,2101.4 1622.34,2035.7 1647.54,2010.5 1801.04,2010.5 1822.74,2032.1 1822.74,2054.6 pad.1@1824.34,2104.6 1824.34,2030.6 1845.14,2009.7 2003.04,2009.7 2023.54,2030.2 ; pad.1@1710.54,3260.8 1801.24,3351.5 1835.34,3385.6 pad.1@2171.54,3385.6 ; pad.1@2023.54,2105.4 2023.54,2030.2 ; pad.1@2198.74,4386.8 2198.74,4269.4 2238.14,4230.1 pad.1@2324.74,4230.1 ; pad.1@2423.54,2105 2423.54,2027.6 ; pad.1@2623.04,2105 2623.04,2029.5 ; pad.1@2720.64,3709.6 2718.34,3669.6 2718.34,3638.7 2738.04,3619 2757.64,3619 2970.24,3619 2986.04,3619 3005.74,3638.7 3005.74,3646.6 3005.74,3674.2 pad.1@3005.74,3717.5 ; 2023.54,2030.2 2045.94,2007.7 2203.84,2007.7 2222.34,2026.2 2222.34,2056.2 pad.1@2222.74,2106.2 2222.74,2024.1 2242.84,2004 2399.94,2004 2423.54,2027.6 ; 2423.54,2027.6 2423.54,2025.5 2443.24,2005.9 2599.44,2005.9 2623.04,2029.5 ; 2623.04,2029.5 2623.04,2028.1 2646.24,2004.8 2802.94,2004.8 2824.24,2026.1 ; 2824.24,2026.1 2825.44,2027.3 2825.44,2053.8 pad.1@2824.24,2103.8 2824.24,2026.1
  Bottom Layer w30: pad.1@1186.14,1123.1 pad.1@1186.14,1575.8
  Bottom Layer w60: pad.1@2198.74,4386.8 3287.24,4386.8
$Net52: pad.1@888.14,4185.6 pad.1@1075.94,4689.9 | length 582.1
  Bottom Layer w15: pad.1@888.14,4185.6 1075.94,4373.4 pad.1@1075.94,4689.9
$Net53: pad.1@1474.34,4689.9
$Net54: pad.1@1574.34,4689.9
$Net55: pad.1@1674.34,4689.9
$Net56: pad.1@1774.34,4689.9
$Net57: pad.1@1974.34,4689.9 pad.1@2068.84,3241.1 | length 1488.5
  Top Layer w15: pad.1@1974.34,4689.9 1973.14,4649.9 1973.14,4565.1 2006.04,4532.2 2012.94,4525.3 2021.54,4516.7 2021.54,3969.4 2021.54,3945.8 2021.54,3319.8 2068.84,3272.6 pad.1@2068.84,3241.1
$Net58: pad.1@2074.34,4689.9 pad.1@2100.34,3241.1 | length 1480.4
  Top Layer w15: pad.1@2074.34,4689.9 2074.34,4596.2 2049.14,4571 2049.14,4534.8 2049.14,4530.9 2049.14,3993.1 2049.14,3977.3 2049.14,3343.5 2100.34,3292.3 pad.1@2100.34,3241.1
$Net59: pad.1@2131.84,3241.1 pad.1@2174.34,4689.9 | length 1499.4
  Top Layer w15: pad.1@2131.84,3241.1 2131.84,3308 2092.44,3347.4 2092.44,4500.9 2129.24,4537.7 2175.14,4583.6 2175.14,4649.9 pad.1@2174.34,4689.9
$Net60: pad.1@2274.34,4689.9
$Net61: pad.1@2374.34,4689.9
$Net62: pad.1@3124.64,4230.1
$Net63: pad.1@2289.24,3241.1 pad.1@2320.74,3709.6 pad.1@2324.74,3930.1 | length 703.1
  Top Layer w15: pad.1@2289.24,3241.1 2289.24,3566.3 2289.24,3597 2322.74,3630.5 2322.74,3669.6 pad.1@2320.74,3709.6
  Bottom Layer w15: pad.1@2320.74,3709.6 2320.74,3880.1 pad.1@2324.74,3930.1
$Net64: pad.1@2320.74,3241.1 pad.1@2420.74,3709.6 pad.1@2424.74,3930.1 | length 730.1
  Top Layer w15: pad.1@2320.74,3241.1 2320.74,3519 2357.74,3556.1 2365.44,3563.7 2419.64,3617.9 2419.64,3669.6 pad.1@2420.74,3709.6
  Bottom Layer w15: pad.1@2420.74,3709.6 2420.74,3880.1 pad.1@2424.74,3930.1
$Net65: pad.1@2352.24,3241.1 pad.1@2520.64,3709.6 pad.1@2524.64,3930.1 | length 758.9
  Top Layer w15: pad.1@2352.24,3241.1 2352.24,3450.5 2459.74,3558 2468.84,3567.1 2520.64,3619 pad.1@2520.64,3709.6
  Bottom Layer w15: pad.1@2520.64,3709.6 2520.64,3880.1 pad.1@2524.64,3930.1
$Net66: pad.1@2383.74,3241.1 pad.1@2620.64,3709.6 pad.1@2624.64,3930.1 | length 787.3
  Top Layer w15: pad.1@2383.74,3241.1 2383.74,3378.1 2567.14,3561.6 2572.64,3567.1 2620.64,3615.1 pad.1@2620.64,3709.6
  Bottom Layer w15: pad.1@2620.64,3709.6 2620.64,3880.1 pad.1@2624.64,3930.1
$Net67: pad.1@1651.44,2340.8
$Net68: pad.1@1522.34,2101.4 pad.1@1751.44,2340.8 pad.1@1990.04,2914.3 | length 1147.6
  Top Layer w15: pad.1@1751.44,2340.8 1749.14,2380.8 1749.14,2563.6 1886.94,2701.4 1886.94,2874.7 1926.64,2914.3 pad.1@1990.04,2914.3
  Bottom Layer w15: pad.1@1522.34,2101.4 1524.34,2151.4 1524.34,2227 1557.34,2260.1 1734.14,2260.1 1751.44,2277.4 pad.1@1751.44,2340.8
$Net69: pad.1@1724.34,2104.6 pad.1@1851.44,2340.8 pad.1@1990.04,2882.8 | length 947.6
  Top Layer w15: pad.1@1851.44,2340.8 1851.44,2597.9 1930.24,2676.6 1930.24,2866 1947.14,2882.8 pad.1@1990.04,2882.8
  Bottom Layer w15: pad.1@1724.34,2104.6 1724.34,2154.6 1724.34,2203.4 1745.14,2224.3 1803.44,2224.3 1816.44,2237.3 1851.44,2272.3 pad.1@1851.44,2340.8
$Net70: pad.1@1923.54,2105.4 pad.1@1951.44,2340.8 pad.1@1990.04,2851.4 | length 772.4
  Top Layer w15: pad.1@1951.44,2340.8 1951.44,2629.4 1990.04,2668 pad.1@1990.04,2851.4
  Bottom Layer w15: pad.1@1923.54,2105.4 1926.64,2155.4 1926.64,2246.7 1951.44,2271.5 pad.1@1951.44,2340.8
$Net71: pad.1@2051.44,2340.8 pad.1@2068.84,2768.8 pad.1@2122.74,2106.2 | length 699.4
  Top Layer w15: pad.1@2051.44,2340.8 2051.44,2662.5 2068.84,2679.8 pad.1@2068.84,2768.8
  Bottom Layer w15: pad.1@2051.44,2340.8 2051.44,2277 2122.74,2205.8 pad.1@2122.74,2106.2
$Net72: pad.1@2100.34,2768.8 pad.1@2151.44,2340.8 pad.1@2323.54,2105 | length 783
  Top Layer w15: pad.1@2100.34,2768.8 2100.34,2677.4 2151.44,2626.2 pad.1@2151.44,2340.8
  Bottom Layer w15: pad.1@2151.44,2340.8 2151.44,2294.7 2251.04,2195.1 2296.74,2195.1 2323.54,2168.4 pad.1@2323.54,2105
$Net73: pad.1@2131.84,2768.8 pad.1@2251.44,2340.8 pad.1@2523.04,2105 | length 948.2
  Top Layer w15: pad.1@2131.84,2768.8 2131.84,2687.3 2253.44,2565.6 2253.44,2380.8 pad.1@2251.44,2340.8
  Bottom Layer w15: pad.1@2251.44,2340.8 pad.1@2253.04,2300.8 ; pad.1@2253.04,2346.7 pad.1@2253.04,2300.8 ; pad.1@2523.04,2105 2523.04,2159.7 2505.74,2177 2495.04,2187.6 2364.84,2187.6 2330.84,2221.7 2318.04,2234.5 2253.04,2299.5 pad.1@2253.04,2300.8
$Net74: pad.1@2163.34,2768.8 pad.1@2351.44,2340.8 pad.1@2724.24,2103.8 | length 1048.1
  Top Layer w15: pad.1@2163.34,2768.8 2163.34,2692.8 2351.44,2504.6 pad.1@2351.44,2340.8
  Bottom Layer w15: pad.1@2351.44,2340.8 2351.44,2282.1 2409.74,2223.9 2667.14,2223.9 2675.84,2215.2 2724.24,2166.8 pad.1@2724.24,2103.8
$Net75: pad.1@2724.24,1803.8 pad.1@2747.04,1577.4 | length 235.8
  Bottom Layer w15: pad.1@2724.24,1803.8 2724.24,1679 2747.04,1656.2 pad.1@2747.04,1577.4
$Net76: pad.1@2824.24,1803.8 pad.1@2864.74,1607.7 | length 212.9
  Bottom Layer w15: pad.1@2824.24,1803.8 2824.24,1753.8 2824.24,1703 2864.74,1662.5 pad.1@2864.74,1607.7
$Net77: pad.1@3763.24,2899.4 pad.1@4106.14,2812.1 | length 418.2
  Top Layer w15: pad.1@3763.24,2899.4 3763.24,2832.5 3783.64,2812.1 pad.1@4106.14,2812.1
$Net78: pad.1@3663.24,2899.4
$Net79: pad.1@3663.24,2599.5 pad.1@3777.34,2745.1 | length 206.7
  Bottom Layer w15: pad.1@3663.24,2599.5 3663.24,2654.6 3753.74,2745.1 pad.1@3777.34,2745.1
$Net80: pad.1@3763.24,2599.5
$Net81: pad.1@3366.34,2899.4 pad.1@3619.84,3016.7 | length 347.7
  Top Layer w15: pad.1@3366.34,2899.4 3366.34,2977.3 3405.74,3016.7 pad.1@3619.84,3016.7
$Net82: pad.1@3266.34,2899.4
$Net83: pad.1@3266.34,2599.5 pad.1@3371.84,2745.1 | length 205.8
  Bottom Layer w15: pad.1@3266.34,2599.5 3265.54,2649.5 3265.54,2650.6 3265.54,2666.4 3344.34,2745.1 pad.1@3371.84,2745.1
$Net84: pad.1@3366.34,2599.5
$Net85: pad.1@3024.64,4230.1
$Net86: pad.1@2924.64,4230.1
$Net87: pad.1@2824.64,4230.1
$Net88: pad.1@2724.64,4230.1
$Net89: pad.1@2624.64,4230.1
$Net90: pad.1@2524.64,4230.1
$Net91: pad.1@2424.74,4230.1
$Net92: pad.1@2816.74,3717.5 pad.1@2824.64,3930.1 | length 215.9
  Bottom Layer w15: pad.1@2816.74,3717.5 2816.74,3792.3 2824.64,3800.1 pad.1@2824.64,3930.1
$Net93: pad.1@2924.64,3930.1 pad.1@2940.74,3717.5 | length 219.1
  Bottom Layer w15: pad.1@2924.64,3930.1 2924.94,3880.1 2924.94,3792.3 2940.74,3776.5 pad.1@2940.74,3717.5
$Net101: pad.1@726.24,2008.9 pad.1@868.04,1851.4 pad.1@868.04,2008.9 | length 299.3
  Top Layer w30: pad.1@726.24,2008.9 pad.1@868.04,2008.9 pad.1@868.04,1851.4
$Net102: pad.1@1086.54,2540.4 pad.1@1175.14,2589.6 | length 126.3
  Top Layer w15: pad.1@1086.54,2540.4 1155.44,2540.4 1175.14,2560.1 pad.1@1175.14,2589.6
$Net103: pad.1@1084.54,2627 pad.1@1175.14,2664.4 | length 105.4
  Top Layer w15: pad.1@1084.54,2627 1104.54,2629 1112.14,2629 1147.54,2664.4 pad.1@1175.14,2664.4
$Net104: pad.1@4143.54,2902.5 pad.1@4145.44,3008.8 | length 106.4
  Top Layer w15: pad.1@4143.54,2902.5 4143.54,2978.8 pad.1@4145.44,3008.8
$Net105: pad.1@3655.34,3252.9 pad.1@3657.24,3107.2 | length 145.8
  Top Layer w15: pad.1@3655.34,3252.9 3657.24,3222.9 pad.1@3657.24,3107.2
$Net106: pad.1@2462.54,3166.3 pad.1@4021.44,3008.8 | length 2070.1
  Top Layer w15: pad.1@2462.54,3166.3 2545.04,3166.3 2560.84,3182 2560.84,3288.3 2627.74,3355.3 3064.74,3355.3 3088.34,3378.9 4005.74,3378.9 4021.44,3363.1 pad.1@4021.44,3008.8
$Net107: pad.1@2462.54,3134.8 pad.1@3531.34,3252.9 | length 1305.5
  Top Layer w15: pad.1@2462.54,3134.8 2584.44,3134.8 2596.24,3146.6 2596.24,3272.6 2647.44,3323.8 3092.34,3323.8 3112.04,3343.5 3505.74,3343.5 3533.24,3315.9 3533.24,3282.9 pad.1@3531.34,3252.9
$Net108: pad.1@1364.04,2670.3 pad.1@1364.04,2839.6 pad.1@1990.04,2977.3 | length 852.3
  Top Layer w15: pad.1@1364.04,2670.3 pad.1@1364.04,2839.6 1525.54,2839.6 1663.34,2977.3 pad.1@1990.04,2977.3
$Net109: pad.1@1755.84,2670.3 pad.1@1757.74,2839.6 pad.1@1990.04,2945.8 | length 475.6
  Top Layer w15: pad.1@1755.84,2670.3 1755.84,2808.1 pad.1@1757.74,2839.6 1757.74,2890.7 1812.94,2945.8 pad.1@1990.04,2945.8
$Net110: pad.1@2462.54,2882.8 pad.1@2800.94,2544.3 pad.1@2905.34,2402.6 | length 884.5
  Top Layer w15: pad.1@2462.54,2882.8 2706.54,2882.8 2730.14,2859.3 2730.14,2564 2749.84,2544.3 2770.94,2544.3 pad.1@2800.94,2544.3 2881.34,2544.3 2907.24,2518.4 2907.24,2432.6 pad.1@2905.34,2402.6
$Net111: pad.1@2462.54,2914.3 pad.1@2800.94,2831.7 pad.1@2887.64,2969.4 | length 613.1
  Top Layer w15: pad.1@2462.54,2914.3 2769.54,2914.3 2800.94,2882.8 pad.1@2800.94,2831.7 2863.94,2831.7 2887.64,2855.4 pad.1@2887.64,2969.4
$Net112: pad.1@2462.54,2945.8 pad.1@2800.94,3189.9 pad.1@2885.64,3048.2 | length 774.9
  Top Layer w15: pad.1@2462.54,2945.8 2761.64,2945.8 2804.94,2989.1 2804.94,3164.9 pad.1@2800.94,3189.9 2830.94,3191.9 2860.04,3191.9 2885.64,3166.3 pad.1@2885.64,3048.2
$Net113: pad.1@2462.54,2977.3 pad.1@2462.54,3040.3 pad.1@2539.24,3040.3 | length 209.8
  Top Layer w15: pad.1@2462.54,2977.3 2517.54,2977.3 2529.34,2977.3 2537.24,2985.2 2537.24,3010.3 pad.1@2539.24,3040.3 2497.44,3040.3 pad.1@2462.54,3040.3
$Net114: pad.1@2194.74,2768.8
$Net115: pad.1@2289.24,2768.8
$Net116: pad.1@2320.74,2768.8
$Net117: pad.1@2352.24,2768.8
$Net118: pad.1@2383.74,2768.8
$Net119: pad.1@2462.54,2851.4
$Net120: pad.1@2462.54,3071.8
$Net121: pad.1@2462.54,3103.3
copper on no net: | length 1543641
  Top Layer w8: 513.64,906.5 513.64,4843.5 4450.64,4843.5 4450.64,906.5 513.64,906.5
